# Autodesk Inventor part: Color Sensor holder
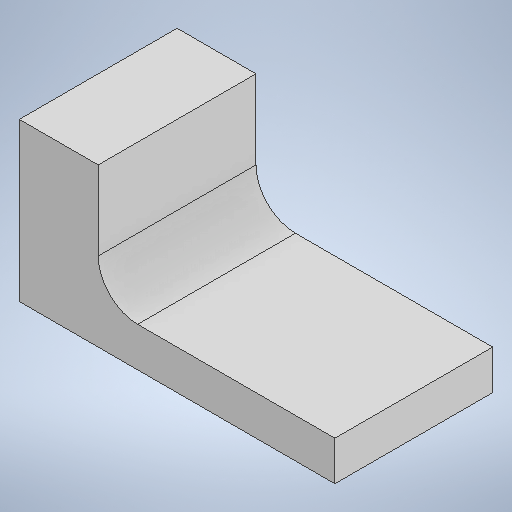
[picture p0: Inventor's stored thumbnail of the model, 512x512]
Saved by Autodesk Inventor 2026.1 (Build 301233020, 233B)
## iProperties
Created: 2026-11
Part Number: Color Sensor holder
Material: Generic
Document SubType Name: Modeling
Designer: hp
Density: 1 g/cm^3
Appearance: Default
Author: hp
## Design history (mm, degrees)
sketch "Sketch1"
  geometry: L1 (0, 0)-(0, 20); L2 (0, 20)-(10, 20); L3 (10, 20)-(10, 5); L4 (10, 5)-(40, 5); L5 (40, 5)-(40, 0); L6 (40, 0)-(0, 0)
  constraints: 12 end point, 5 perpendicular, 1 vertical
  dimensions: "d0" = 20 distance of L1.start L1.end; "d1" = 10 distance of L1.end L2.end; "d2" = 15 distance of L2.end L3.end; "d3" = 30 distance of L3.end L4.end
extrude "Extrusion1" new body sketch "Sketch1" distance "d4" = 20; taper "d5" = 0 deg
fillet "Fillet1" dims "d6" = 5
body "Solid1"
